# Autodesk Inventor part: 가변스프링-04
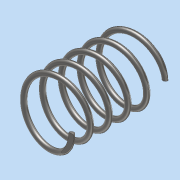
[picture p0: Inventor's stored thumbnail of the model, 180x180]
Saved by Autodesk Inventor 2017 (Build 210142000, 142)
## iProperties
Part Number: 가변스프링-04
Material: 강철, 연강
Document SubType Name: Modeling
Designer: MRC
Density: 7.85 g/cm^3
Appearance: 반연마
Mass: 8.42324 g
Surface Area: 21.7217 cm^2
Volume: 1.07302 cm^3
Author: MRC
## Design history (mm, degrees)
sketch "스케치1"
  geometry: L1 (0, 0)-(11, 0); L2 (11, 0)-(11, 36.411); L3 (11, 36.411)-(0, 36.411); L4 (0, 36.411)-(0, 0); C1 r 1 at (11, 0)
  constraints: 8 end point, 2 parallel, 1 centre point, 1 coincident, 1 horizontal, 1 perpendicular
  dimensions: "d0" = 36.4112 distance of L3.end L1.start (derived); "d1" = 22 diameter of L2 L4; "d2" = 2 diameter of C1
feature "코일1" sketch "스케치1" pitch "d3" = 10; turns "d5" = 5; dims "d4" = 36.4112 (= d0), "d6" = 0, angle "d7" = 90 deg, angle "d8" = 90 deg, "d9" = 0, "d10" = 0
sketch "스케치2"
  geometry: L1 (36.411, 17.383)-(0, 17.383); L2 (0, 17.383)-(0, -17.383); L3 (0, -17.383)-(36.411, -17.383); L4 (36.411, -17.383)-(36.411, 17.383); 2 further points
  constraints: 8 end point, 2 parallel, 1 coincident, 1 horizontal, 1 midpoint, 1 perpendicular
  dimensions: "d11" = 36.4112 distance of L2.end L3.end (= d0); "d12" = 34.76604 distance of L3.end L1.start
extrude "돌출1" sketch "스케치2" stored distance "d13" = 47.75; taper "d14" = 0 deg
node "솔리드1"
